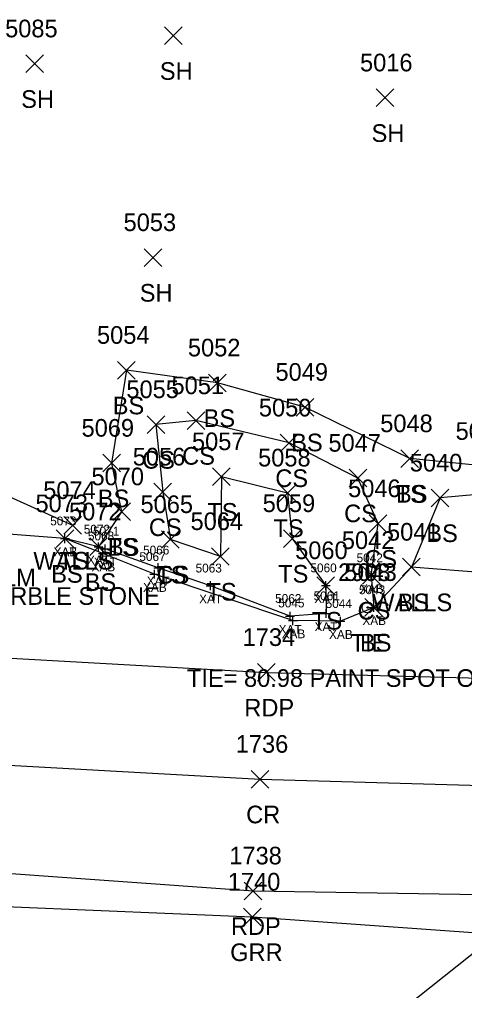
# Model space of a CAD drawing. Extents: x 1509053 to 1511576, y 400838 to 402572.
# Drawn here: x 1510343.8 to 1510394.2, y 401626.6 to 401736.7 of the extents above; entities that cross this region are included whole.
import ezdxf

# ---------------------------------------------------------------- set-up
doc = ezdxf.new("R2010")
doc.units = 0
for name, color, linetype in [('B_A', 7, 'Continuous'), ('B_I', 7, 'Continuous'), ('B_TIC', 7, 'Continuous'), ('BSUBM', 7, 'Continuous'), ('C_A', 7, 'Continuous'), ('C_C', 7, 'Continuous'), ('C_I', 7, 'Continuous'), ('CBP', 7, 'Continuous'), ('DCP', 7, 'Continuous'), ('L_A', 7, 'Continuous'), ('L_C', 7, 'Continuous'), ('L_I', 7, 'Continuous'), ('L_TIC', 7, 'Continuous'), ('LELB', 7, 'Continuous'), ('LWS', 7, 'Continuous'), ('P_A', 7, 'Continuous'), ('P_I', 7, 'Continuous'), ('P_TIC', 7, 'Continuous'), ('PET', 7, 'Continuous'), ('PRC', 7, 'Continuous'), ('R_A', 7, 'Continuous'), ('R_I', 7, 'Continuous'), ('R_TIC', 7, 'Continuous'), ('RGR', 7, 'Continuous')]:
    doc.layers.add(name, color=color, linetype=linetype)

msp = doc.modelspace()

# ---------------------------------------------------------------- linework, layer by layer
at = {"layer": 'B_TIC'}
for p, q in [((1510348.93, 401677.81), (1510349.01, 401677.81)), ((1510348.93, 401677.81), (1510349.01, 401677.81)), ((1510352.73, 401676.88), (1510352.81, 401676.88)), ((1510353.5, 401676.66), (1510353.58, 401676.66)), ((1510353.23, 401676.11), (1510353.31, 401676.11)), ((1510359.5, 401674.51), (1510359.57, 401674.51)), ((1510359.06, 401673.77), (1510359.14, 401673.77)), ((1510383.64, 401673.63), (1510383.72, 401673.63)), ((1510365.43, 401672.47), (1510365.5, 401672.47)), ((1510378.48, 401672.49), (1510378.56, 401672.49)), ((1510383.91, 401670.01), (1510383.99, 401670.01)), ((1510374.44, 401669.02), (1510374.51, 401669.02)), ((1510378.51, 401669.32), (1510378.59, 401669.32)), ((1510374.76, 401668.51), (1510374.84, 401668.51)), ((1510380.13, 401668.44), (1510380.21, 401668.44))]:
    msp.add_line(p, q, dxfattribs=at)
for points in [[(1510348.43, 401677.81), (1510349.43, 401677.81)], [(1510348.43, 401677.81), (1510349.43, 401677.81)], [(1510348.93, 401677.31), (1510348.93, 401678.31)], [(1510348.93, 401677.31), (1510348.93, 401678.31)], [(1510352.23, 401676.88), (1510353.23, 401676.88)], [(1510352.73, 401676.38), (1510352.73, 401677.38)], [(1510353, 401676.66), (1510354, 401676.66)], [(1510353.23, 401675.61), (1510353.23, 401676.61)], [(1510353.5, 401676.16), (1510353.5, 401677.16)], [(1510352.73, 401676.11), (1510353.73, 401676.11)], [(1510359, 401674.51), (1510360, 401674.51)], [(1510359.06, 401673.27), (1510359.06, 401674.27)], [(1510359.5, 401674.01), (1510359.5, 401675.01)], [(1510383.64, 401673.13), (1510383.64, 401674.13)], [(1510358.56, 401673.77), (1510359.56, 401673.77)], [(1510378.48, 401671.99), (1510378.48, 401672.99)], [(1510383.14, 401673.63), (1510384.14, 401673.63)], [(1510364.93, 401672.47), (1510365.93, 401672.47)], [(1510365.43, 401671.97), (1510365.43, 401672.97)], [(1510377.98, 401672.49), (1510378.98, 401672.49)], [(1510378.51, 401668.82), (1510378.51, 401669.82)], [(1510383.41, 401670.01), (1510384.41, 401670.01)], [(1510383.91, 401669.51), (1510383.91, 401670.51)], [(1510373.93, 401669.02), (1510374.93, 401669.02)], [(1510374.43, 401668.52), (1510374.43, 401669.52)], [(1510374.76, 401668.01), (1510374.76, 401669.01)], [(1510378.01, 401669.32), (1510379.01, 401669.32)], [(1510380.13, 401667.94), (1510380.13, 401668.94)], [(1510374.26, 401668.51), (1510375.26, 401668.51)], [(1510379.63, 401668.44), (1510380.63, 401668.44)]]:
    msp.add_lwpolyline(points, dxfattribs=at)
at = {"layer": 'BSUBM'}
for points in [[(1510383.64, 401673.63), (1510383.91, 401670.01), (1510380.13, 401668.44), (1510374.76, 401668.51), (1510359.06, 401673.77), (1510353.23, 401676.11), (1510348.93, 401677.81)], [(1510378.48, 401672.49), (1510378.51, 401669.32), (1510374.43, 401669.02), (1510365.43, 401672.47), (1510359.5, 401674.51), (1510353.5, 401676.66), (1510352.73, 401676.88), (1510348.93, 401677.81)]]:
    msp.add_lwpolyline(points, dxfattribs=at)
at = {"layer": 'CBP'}
for radius in [0.625, 0.0833]:
    msp.add_circle((1510383.21, 401670), radius, dxfattribs=at)
at = {"layer": 'DCP'}
msp.add_lwpolyline([(1510342.37, 401588.83), (1510435.52, 401662.91)], dxfattribs=at)
at = {"layer": 'L_TIC'}
for points in [[(1510360.19, 401733.83), (1510362.19, 401735.83)], [(1510362.19, 401733.83), (1510360.19, 401735.83)], [(1510344.49, 401730.65), (1510346.49, 401732.65)], [(1510346.49, 401730.65), (1510344.49, 401732.65)], [(1510384.18, 401726.79), (1510386.18, 401728.79)], [(1510386.18, 401726.79), (1510384.18, 401728.79)], [(1510357.91, 401708.68), (1510359.91, 401710.68)], [(1510359.91, 401708.68), (1510357.91, 401710.68)], [(1510354.9, 401695.9), (1510356.9, 401697.9)], [(1510356.9, 401695.9), (1510354.9, 401697.9)], [(1510365.2, 401694.47), (1510367.2, 401696.47)], [(1510367.2, 401694.47), (1510365.2, 401696.47)], [(1510375.12, 401691.71), (1510377.12, 401693.71)], [(1510377.12, 401691.71), (1510375.12, 401693.71)], [(1510358.23, 401689.74), (1510360.23, 401691.74)], [(1510360.23, 401689.74), (1510358.23, 401691.74)], [(1510362.77, 401690.19), (1510364.77, 401692.19)], [(1510364.77, 401690.19), (1510362.77, 401692.19)], [(1510373.32, 401687.66), (1510375.32, 401689.66)], [(1510375.32, 401687.66), (1510373.32, 401689.66)], [(1510353.21, 401685.37), (1510355.21, 401687.37)], [(1510355.21, 401685.37), (1510353.21, 401687.37)], [(1510386.99, 401685.88), (1510388.99, 401687.88)], [(1510388.99, 401685.88), (1510386.99, 401687.88)], [(1510386.99, 401685.88), (1510388.99, 401687.88)], [(1510388.99, 401685.88), (1510386.99, 401687.88)], [(1510365.65, 401683.84), (1510367.65, 401685.84)], [(1510367.65, 401683.84), (1510365.65, 401685.84)], [(1510365.65, 401683.84), (1510367.65, 401685.84)], [(1510367.65, 401683.84), (1510365.65, 401685.84)], [(1510381.12, 401683.67), (1510383.12, 401685.67)], [(1510383.12, 401683.67), (1510381.12, 401685.67)], [(1510359, 401682.1), (1510361, 401684.1)], [(1510361, 401682.1), (1510359, 401684.1)], [(1510373.15, 401681.99), (1510375.15, 401683.99)], [(1510375.15, 401681.99), (1510373.15, 401683.99)], [(1510390.43, 401681.42), (1510392.43, 401683.42)], [(1510392.43, 401681.42), (1510390.43, 401683.42)], [(1510354.35, 401679.86), (1510356.35, 401681.86)], [(1510356.35, 401679.86), (1510354.35, 401681.86)], [(1510354.35, 401679.86), (1510356.35, 401681.86)], [(1510356.35, 401679.86), (1510354.35, 401681.86)], [(1510348.81, 401678.3), (1510350.81, 401680.3)], [(1510350.81, 401678.3), (1510348.81, 401680.3)], [(1510348.81, 401678.3), (1510350.81, 401680.3)], [(1510350.81, 401678.3), (1510348.81, 401680.3)], [(1510383.4, 401678.51), (1510385.4, 401680.51)], [(1510385.4, 401678.51), (1510383.4, 401680.51)], [(1510347.93, 401676.81), (1510349.93, 401678.81)], [(1510349.93, 401676.81), (1510347.93, 401678.81)], [(1510359.87, 401676.71), (1510361.87, 401678.71)], [(1510361.87, 401676.71), (1510359.87, 401678.71)], [(1510359.87, 401676.71), (1510361.87, 401678.71)], [(1510361.87, 401676.71), (1510359.87, 401678.71)], [(1510373.68, 401676.82), (1510375.68, 401678.82)], [(1510375.68, 401676.82), (1510373.68, 401678.82)], [(1510351.73, 401675.88), (1510353.73, 401677.88)], [(1510353.73, 401675.88), (1510351.73, 401677.88)], [(1510365.55, 401674.78), (1510367.55, 401676.78)], [(1510367.55, 401674.78), (1510365.55, 401676.78)], [(1510387.19, 401673.58), (1510389.19, 401675.58)], [(1510389.19, 401673.58), (1510387.19, 401675.58)], [(1510387.19, 401673.58), (1510389.19, 401675.58)], [(1510389.19, 401673.58), (1510387.19, 401675.58)], [(1510382.64, 401672.63), (1510384.64, 401674.63)], [(1510384.64, 401672.63), (1510382.64, 401674.63)], [(1510377.48, 401671.49), (1510379.48, 401673.49)], [(1510379.48, 401671.49), (1510377.48, 401673.49)], [(1510382.91, 401669.01), (1510384.91, 401671.01)], [(1510384.91, 401669.01), (1510382.91, 401671.01)]]:
    msp.add_lwpolyline(points, dxfattribs=at)
at = {"layer": 'LELB'}
for points in [[(1510398.52, 401730.98), (1510401.25, 401703.15), (1510403.99, 401691.71), (1510396.54, 401686.01), (1510387.99, 401686.88)], [(1510404.13, 401706.22), (1510408.54, 401691.35), (1510397.79, 401683.01), (1510391.43, 401682.42), (1510388.19, 401674.58), (1510383.91, 401670.01)], [(1510387.99, 401686.88), (1510376.12, 401692.71), (1510366.2, 401695.47), (1510355.9, 401696.9), (1510354.21, 401686.37), (1510355.35, 401680.86), (1510352.73, 401676.88)], [(1510383.64, 401673.63), (1510384.4, 401679.51), (1510382.12, 401684.67), (1510374.32, 401688.66), (1510363.77, 401691.19), (1510359.23, 401690.74), (1510360, 401683.1), (1510360.87, 401677.71)], [(1510366.65, 401684.84), (1510366.55, 401675.78), (1510360.87, 401677.71)], [(1510366.65, 401684.84), (1510374.15, 401682.99), (1510374.68, 401677.82), (1510378.48, 401672.49)], [(1510348.93, 401677.81), (1510331.2, 401679.18)]]:
    msp.add_lwpolyline(points, dxfattribs=at)
at = {"layer": 'LWS'}
for points in [[(1510349.81, 401679.3), (1510337.11, 401685.04), (1510331.2, 401679.18), (1510316.95, 401676.48), (1510297.59, 401679.14), (1510269.51, 401678.15), (1510244.84, 401677.73), (1510225.49, 401677.12), (1510218.49, 401676.76), (1510185.87, 401675.88)], [(1510408.54, 401672.98), (1510388.19, 401674.58)]]:
    msp.add_lwpolyline(points, dxfattribs=at)
at = {"layer": 'P_TIC'}
for points in [[(1510370.76, 401661.64), (1510372.76, 401663.64)], [(1510372.76, 401661.64), (1510370.76, 401663.64)], [(1510370.03, 401649.53), (1510372.03, 401651.53)], [(1510372.03, 401649.53), (1510370.03, 401651.53)], [(1510369.24, 401636.87), (1510371.24, 401638.87)], [(1510371.24, 401636.87), (1510369.24, 401638.87)]]:
    msp.add_lwpolyline(points, dxfattribs=at)
at = {"layer": 'PET'}
for points in [[(1510069.7, 401647.38), (1510070.82, 401637.95), (1510072.41, 401628.04), (1510122.3, 401634.81), (1510170.19, 401640.65), (1510220.23, 401643.86), (1510269.72, 401644.29), (1510320.63, 401641.42), (1510370.24, 401637.87), (1510421.73, 401637.03), (1510472.3, 401638.25), (1510523.24, 401640.81), (1510571.7, 401643.53), (1510622.45, 401646.41), (1510672.72, 401649.13), (1510722.86, 401651.91), (1510723.41, 401651.94), (1510773.15, 401654.37), (1510822.4, 401657.74), (1510872.35, 401660.8), (1510922.85, 401663.95), (1510967.23, 401666.49), (1511034, 401670.65), (1511071.49, 401673.22)], [(1510068.52, 401654.76), (1510069.7, 401647.38), (1510117.95, 401657.12), (1510168.51, 401664.21), (1510212.05, 401667), (1510220.39, 401667.36), (1510271.44, 401667.79), (1510321.9, 401665.44), (1510371.76, 401662.64), (1510420.35, 401661.34), (1510470.43, 401662.43), (1510520.33, 401664.72), (1510570.63, 401667.06), (1510593.1, 401669.05), (1510621.58, 401670.53), (1510656.11, 401672.66)]]:
    msp.add_lwpolyline(points, dxfattribs=at)
at = {"layer": 'PRC'}
msp.add_lwpolyline([(1510070.82, 401637.95), (1510120.23, 401645.42), (1510169.76, 401652.13), (1510220.07, 401655.52), (1510220.14, 401655.43), (1510270.51, 401655.53), (1510320.84, 401653.34), (1510371.03, 401650.53), (1510421.26, 401649.11), (1510471.33, 401650.1), (1510521.34, 401652.38), (1510571.58, 401655.12), (1510621.67, 401657.75), (1510671.66, 401660.66), (1510722.15, 401663.46), (1510772.15, 401666.42), (1510822.28, 401669.1), (1510872.26, 401671.98), (1510872.29, 401672.01), (1510922.21, 401674.96), (1510971.31, 401678.08), (1511022.51, 401681.61), (1511070.2, 401684.98)], dxfattribs=at)
at = {"layer": 'R_TIC'}
for points in [[(1510369.16, 401633.92), (1510371.16, 401635.92)], [(1510371.16, 401633.92), (1510369.16, 401635.92)]]:
    msp.add_lwpolyline(points, dxfattribs=at)
at = {"layer": 'RGR'}
msp.add_lwpolyline([(1510073.99, 401627.51), (1510122.46, 401632.98), (1510170.64, 401638.74), (1510220.08, 401641.84), (1510269.6, 401641.85), (1510311.11, 401639.49), (1510334.05, 401636.42), (1510370.16, 401634.91), (1510403.15, 401632.59)], dxfattribs=at)

# ---------------------------------------------------------------- texts
at = {"layer": 'B_A'}
for s, p in [('XAT', (1510347.63, 401675.81)), ('XAB', (1510347.65, 401675.81)), ('XAT', (1510351.43, 401674.88)), ('XAT', (1510352.2, 401674.66)), ('XAB', (1510351.95, 401674.11)), ('XAT', (1510358.2, 401672.51)), ('XAB', (1510357.78, 401671.77)), ('XAB', (1510382.36, 401671.63)), ('XAT', (1510364.13, 401670.47)), ('XAT', (1510377.18, 401670.49)), ('XAB', (1510382.63, 401668.01)), ('XAT', (1510373.14, 401667.02)), ('XAB', (1510373.48, 401666.51)), ('XAT', (1510377.21, 401667.32)), ('XAB', (1510378.85, 401666.44))]:
    msp.add_text(s, height=1, dxfattribs=at).set_placement(p)
at = {"layer": 'B_I'}
for s, p in [('5073', (1510347.26, 401679.31)), ('5073', (1510347.26, 401679.31)), ('5072', (1510351.06, 401678.38)), ('5068', (1510351.53, 401677.61)), ('5071', (1510352.11, 401678.16)), ('5066', (1510357.78, 401676.01)), ('5067', (1510357.36, 401675.27)), ('5042', (1510381.97, 401675.13)), ('5063', (1510363.73, 401673.97)), ('5060', (1510376.74, 401673.99)), ('5043', (1510382.24, 401671.51)), ('5062', (1510372.74, 401670.52)), ('5045', (1510373.09, 401670.01)), ('5061', (1510377.1, 401670.82)), ('5044', (1510378.46, 401669.94))]:
    msp.add_text(s, height=1, dxfattribs=at).set_placement(p)
at = {"layer": 'C_A'}
msp.add_text('TIE', height=2, dxfattribs=at).set_placement((1510381.29, 401665))
at = {"layer": 'C_C'}
msp.add_text('TIE= 80.98 PAINT SPOT ON', height=2, dxfattribs=at).set_placement((1510362.75, 401661))
at = {"layer": 'C_I'}
msp.add_text('2908', height=2, dxfattribs=at).set_placement((1510379.87, 401673))
at = {"layer": 'L_A'}
for s, p in [('SH', (1510359.68, 401729.83)), ('SH', (1510343.97, 401726.65)), ('SH', (1510383.67, 401722.79)), ('SH', (1510357.4, 401704.68)), ('BS', (1510354.34, 401691.9)), ('BS', (1510364.64, 401690.47)), ('BS', (1510374.56, 401687.71)), ('CS', (1510357.67, 401685.74)), ('CS', (1510362.21, 401686.19)), ('CS', (1510372.76, 401683.66)), ('BS', (1510352.65, 401681.37)), ('TS', (1510386.4, 401681.88)), ('BS', (1510386.43, 401681.88)), ('TS', (1510365.06, 401679.84)), ('TS', (1510365.06, 401679.84)), ('CS', (1510380.56, 401679.67)), ('CS', (1510358.44, 401678.1)), ('TS', (1510372.56, 401677.99)), ('BS', (1510389.87, 401677.42)), ('TS', (1510353.76, 401675.86)), ('BS', (1510353.79, 401675.86)), ('WALLS', (1510345.35, 401674.3)), ('TS', (1510348.22, 401674.3)), ('CS', (1510382.84, 401674.51)), ('BS', (1510347.37, 401672.81)), ('TS', (1510359.28, 401672.71)), ('CS', (1510359.31, 401672.71)), ('TS', (1510373.09, 401672.82)), ('BS', (1510351.17, 401671.88)), ('TS', (1510364.96, 401670.78)), ('WALLS', (1510383.74, 401669.58)), ('BS', (1510386.63, 401669.58)), ('CS', (1510382.08, 401668.63)), ('TS', (1510376.89, 401667.49)), ('BS', (1510382.35, 401665.01))]:
    msp.add_text(s, height=2, dxfattribs=at).set_placement(p)
at = {"layer": 'L_C'}
for s, p in [('2S.ELM', (1510336.11, 401672.39)), ('MARBLE STONE', (1510338.72, 401670.3))]:
    msp.add_text(s, height=2, dxfattribs=at).set_placement(p)
at = {"layer": 'L_I'}
for s, p in [('5085', (1510342.15, 401734.65)), ('5016', (1510382.36, 401730.79)), ('5053', (1510355.57, 401712.68)), ('5054', (1510352.56, 401699.9)), ('5052', (1510362.86, 401698.47)), ('5049', (1510372.78, 401695.71)), ('5051', (1510361, 401694.19)), ('5055', (1510355.89, 401693.74)), ('5050', (1510370.9, 401691.66)), ('5048', (1510384.65, 401689.88)), ('5048', (1510384.65, 401689.88)), ('5069', (1510350.81, 401689.37)), ('5039', (1510393.19, 401689.01)), ('5057', (1510363.32, 401687.84)), ('5057', (1510363.32, 401687.84)), ('5047', (1510378.78, 401687.67)), ('5056', (1510356.61, 401686.1)), ('5058', (1510370.81, 401685.99)), ('5040', (1510388, 401685.42)), ('5070', (1510351.93, 401683.86)), ('5070', (1510351.93, 401683.86)), ('5074', (1510346.47, 401682.3)), ('5074', (1510346.47, 401682.3)), ('5046', (1510381.01, 401682.51)), ('5073', (1510345.59, 401680.81)), ('5072', (1510349.39, 401679.88)), ('5065', (1510357.49, 401680.71)), ('5065', (1510357.49, 401680.71)), ('5059', (1510371.33, 401680.82)), ('5064', (1510363.16, 401678.78)), ('5041', (1510385.42, 401677.58)), ('5041', (1510385.42, 401677.58)), ('5042', (1510380.3, 401676.63)), ('5060', (1510375.01, 401675.49)), ('5043', (1510380.57, 401673.01))]:
    msp.add_text(s, height=2, dxfattribs=at).set_placement(p)
at = {"layer": 'P_A'}
for s, p in [('RDP', (1510369.25, 401657.64)), ('CR', (1510369.46, 401645.53)), ('RDP', (1510367.73, 401632.87))]:
    msp.add_text(s, height=2, dxfattribs=at).set_placement(p)
at = {"layer": 'P_I'}
for s, p in [('1734', (1510369.06, 401665.64)), ('1736', (1510368.28, 401653.53)), ('1738', (1510367.55, 401640.87))]:
    msp.add_text(s, height=2, dxfattribs=at).set_placement(p)
at = {"layer": 'R_A'}
msp.add_text('GRR', height=2, dxfattribs=at).set_placement((1510367.65, 401629.91))
at = {"layer": 'R_I'}
msp.add_text('1740', height=2, dxfattribs=at).set_placement((1510367.38, 401637.91))

doc.saveas('drawing.dxf')
